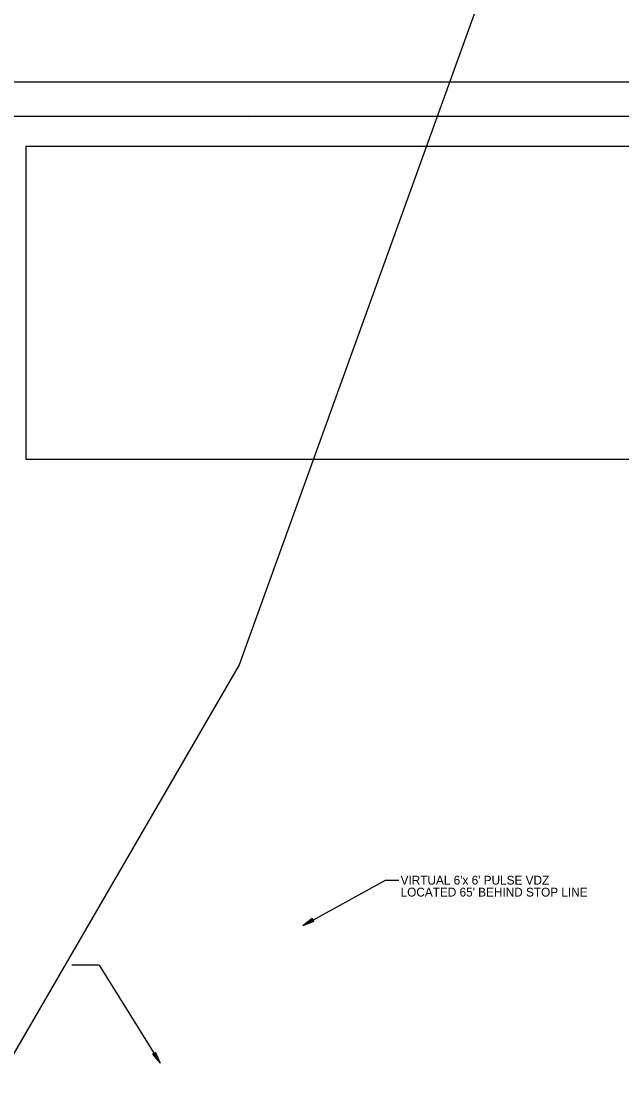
# Model space of a CAD drawing. Extents: x 660636 to 661659, y 641779 to 643841.
# Drawn here: x 661075.8 to 661280.2, y 642584.7 to 642944.6 of the extents above; entities that cross this region are included whole.
import ezdxf

# ---------------------------------------------------------------- set-up
doc = ezdxf.new("R2010")
doc.units = 0
for name, color, linetype in [('Default', 7, 'Continuous'), ('R_Border', 7, 'Continuous'), ('R_No Plot', 7, 'Continuous'), ('T_Drafting', 7, 'Continuous')]:
    doc.layers.add(name, color=color, linetype=linetype)

msp = doc.modelspace()

# ---------------------------------------------------------------- linework, layer by layer
at = {"layer": 'Default'}
msp.add_lwpolyline([(661077.35, 642795.58), (661326.48, 642795.58), (661326.48, 642901.91), (661077.35, 642901.91)], close=True, dxfattribs=at)
at = {"layer": 'R_Border'}
for p, q in [((660695.76, 642912.31), (661644.3, 642912.31)), ((661153.32, 642911.53), (661153.32, 642911.53)), ((661153.32, 642911.53), (661153.32, 642911.53))]:
    msp.add_line(p, q, dxfattribs=at)
at = {"layer": 'R_No Plot'}
msp.add_line((660658.55, 642924), (661658.55, 642924), dxfattribs=at)
msp.add_lwpolyline([(660658.53, 642924), (661658.55, 642924), (661658.55, 642283.98), (660658.53, 642283.98)], close=True, dxfattribs=at)
at = {"layer": 'T_Drafting'}
for p, q in [((661199.67, 642652.18), (661171.64, 642636.82)), ((661204.26, 642652.18), (661199.67, 642652.18)), ((661174.86, 642639.27), (661171.64, 642636.82)), ((661175.44, 642638.22), (661171.64, 642636.82)), ((661174.91, 642639.18), (661172.23, 642637.14)), ((661175.39, 642638.3), (661172.23, 642637.14)), ((661174.96, 642639.09), (661172.83, 642637.47)), ((661175.34, 642638.39), (661172.83, 642637.47)), ((661175.01, 642639), (661173.41, 642637.79)), ((661175.29, 642638.48), (661173.41, 642637.79)), ((661175.05, 642638.91), (661174.01, 642638.12)), ((661175.24, 642638.57), (661174.01, 642638.12)), ((661175.1, 642638.82), (661174.59, 642638.44)), ((661175.19, 642638.66), (661174.59, 642638.44)), ((661175.44, 642638.22), (661174.86, 642639.27)), ((661102.32, 642623.41), (661093.09, 642623.41)), ((661102.32, 642623.41), (661123.15, 642589.99)), ((661121.54, 642593.7), (661120.52, 642593.06)), ((661120.52, 642593.06), (661123.15, 642589.99)), ((661120.61, 642593.12), (661122.8, 642590.55)), ((661120.69, 642593.17), (661122.43, 642591.14)), ((661120.78, 642593.22), (661122.08, 642591.7)), ((661120.87, 642593.28), (661121.72, 642592.28)), ((661120.95, 642593.33), (661121.37, 642592.84)), ((661121.11, 642593.43), (661121.37, 642592.84)), ((661121.2, 642593.48), (661121.72, 642592.28)), ((661121.29, 642593.54), (661122.08, 642591.7)), ((661121.37, 642593.59), (661122.43, 642591.14)), ((661121.46, 642593.65), (661122.8, 642590.55)), ((661121.54, 642593.7), (661123.15, 642589.99))]:
    msp.add_line(p, q, dxfattribs=at)
msp.add_lwpolyline([(661266.39, 643047.99), (661150, 642725.53), (660636.16, 641839.68)], dxfattribs=at)
msp.add_lwpolyline([(661266.39, 643047.99), (661150, 642725.53), (660636.16, 641839.68)], dxfattribs=at)
msp.add_lwpolyline([(661266.39, 643047.99), (661150, 642725.53), (660636.16, 641839.68)], dxfattribs=at)

# ---------------------------------------------------------------- texts
for s, p in [("VIRTUAL 6'x 6' PULSE VDZ", (661204.91, 642650.81)), ("LOCATED 65' BEHIND STOP LINE", (661204.91, 642646.74))]:
    msp.add_text(s, height=3, dxfattribs=at).set_placement(p)

doc.saveas('drawing.dxf')
